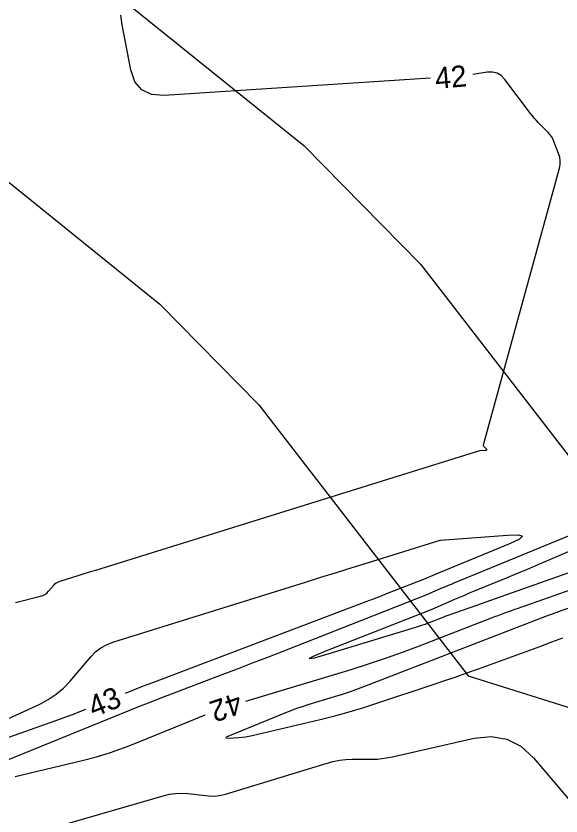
# Model space of a CAD drawing. Extents: x 2384780 to 2405861, y 547869 to 573706.
# Drawn here: x 2389996.9 to 2390047.8, y 552537.2 to 552612 of the extents above; entities that cross this region are included whole.
import ezdxf

# ---------------------------------------------------------------- set-up
doc = ezdxf.new("R2010")
doc.units = 0
for name, color, linetype in [('Old_Level_60', 7, 'Continuous'), ('Prop Buffer Zone 1', 7, 'Continuous'), ('Prop Buffer Zone 2', 7, 'Continuous')]:
    doc.layers.add(name, color=color, linetype=linetype)

msp = doc.modelspace()

# ---------------------------------------------------------------- linework, layer by layer
at = {"layer": 'Old_Level_60'}
for points in [[(2390035.611, 552606.14625), (2390010.736, 552604.53775), (2390009.56225, 552604.6245), (2390008.653, 552605.05375), (2390008.00825, 552605.82525), (2390007.62825, 552606.93925), (2390006.81925, 552611.13775), (2390006.67725, 552612.039)], [(2389996.85825, 552557.1455), (2389999.17375, 552557.72175), (2389999.39, 552557.793), (2389999.58775, 552557.8945), (2389999.7665, 552558.02625), (2389999.92675, 552558.18825), (2390000.41925, 552558.767), (2390000.531, 552558.88175), (2390000.65525, 552558.97725), (2390000.792, 552559.05425), (2390000.94125, 552559.11225), (2390002.7825, 552559.687), (2390003.17725, 552559.81), (2390003.57175, 552559.933), (2390003.9665, 552560.056), (2390004.361, 552560.179), (2390040.23375, 552571.3425), (2390040.23375, 552571.3425), (2390040.23375, 552571.3425), (2390040.23375, 552571.3425), (2390040.23375, 552571.3425), (2390040.234, 552571.3425), (2390040.234, 552571.3425), (2390040.234, 552571.3425), (2390040.234, 552571.3425), (2390040.234, 552571.3425), (2390040.804, 552571.38575), (2390040.86875, 552571.398), (2390040.8975, 552571.42275), (2390040.88975, 552571.45975), (2390040.8455, 552571.509), (2390040.642, 552571.69), (2390040.60575, 552571.731), (2390040.58425, 552571.77625), (2390040.57775, 552571.826), (2390040.58575, 552571.88), (2390047.6805, 552597.74025), (2390047.7485, 552598.0925), (2390047.7585, 552598.4415), (2390047.7105, 552598.78725), (2390047.6045, 552599.13), (2390047.16375, 552600.24425), (2390047.05875, 552600.47625), (2390046.9325, 552600.6945), (2390046.78525, 552600.899), (2390046.61675, 552601.08975), (2390045.70825, 552602.02325), (2390045.517, 552602.22625), (2390045.3325, 552602.435), (2390045.1545, 552602.64925), (2390044.98325, 552602.86925), (2390042.58725, 552606.0485), (2390042.24975, 552606.40125), (2390041.86225, 552606.62975), (2390041.42475, 552606.7345), (2390040.937, 552606.71525), (2390039.593, 552606.50225)], [(2390062.94525, 552568.0865), (2390046.32475, 552560.94525), (2390045.45975, 552560.5755), (2390044.5935, 552560.20925), (2390043.72575, 552559.846), (2390042.85675, 552559.48625), (2390039.71475, 552558.19275), (2390039.2565, 552558.00275), (2390038.7995, 552557.8105), (2390038.34325, 552557.61575), (2390037.88825, 552557.4185), (2390035.76775, 552556.4935), (2390035.76725, 552556.49325), (2390035.76675, 552556.493), (2390035.76625, 552556.49275), (2390035.76575, 552556.49275), (2390035.76425, 552556.492), (2390035.76375, 552556.492), (2390035.7635, 552556.49175), (2390035.76325, 552556.49175), (2390035.76275, 552556.4915), (2390026.063, 552552.67275), (2390024.72875, 552552.12625), (2390024.30125, 552551.895), (2390024.78, 552551.979), (2390026.1655, 552552.37775), (2390033.94, 552554.73), (2390034.342, 552554.85575), (2390034.7415, 552554.989), (2390035.13825, 552555.13), (2390035.5325, 552555.2785), (2390036.816, 552555.77575), (2390037.09125, 552555.88125), (2390037.3675, 552555.9845), (2390037.6445, 552556.08575), (2390037.92225, 552556.185), (2390039.95475, 552556.90075), (2390040.39025, 552557.05425), (2390040.82575, 552557.20775), (2390041.26125, 552557.361), (2390041.697, 552557.5145), (2390053.17325, 552561.55725)], [(2390053.189, 552565.2745), (2390037.81475, 552558.94525), (2390037.551, 552558.836), (2390037.2875, 552558.725), (2390037.02475, 552558.61275), (2390036.76275, 552558.49925), (2390035.5445, 552557.96775), (2390035.5425, 552557.967), (2390035.5405, 552557.96625), (2390035.5385, 552557.96525), (2390035.5365, 552557.9645), (2390035.53, 552557.962), (2390035.5285, 552557.9615), (2390035.527, 552557.961), (2390035.52575, 552557.9605), (2390035.52425, 552557.96), (2390021.82, 552552.5645), (2390020.40125, 552552.00825), (2390018.98075, 552551.4565), (2390017.5585, 552550.909), (2390016.1345, 552550.366), (2390011.4805, 552548.599), (2390010.48425, 552548.21775), (2390009.49025, 552547.83075), (2390008.4985, 552547.43825), (2390007.50875, 552547.04025), (2389994.6135, 552541.81225)], [(2389989.377, 552543.18375), (2389999.10925, 552547.6485), (2389999.909, 552548.06825), (2390000.649, 552548.5665), (2390001.3295, 552549.1435), (2390001.95075, 552549.799), (2390003.8825, 552552.069), (2390004.32075, 552552.51825), (2390004.80825, 552552.89375), (2390005.3445, 552553.195), (2390005.92975, 552553.4225), (2390023.93975, 552559.0445), (2390025.39275, 552559.49775), (2390026.84575, 552559.95075), (2390028.299, 552560.4035), (2390029.75225, 552560.856), (2390036.52875, 552562.96475), (2390036.5315, 552562.96575), (2390036.5345, 552562.96675), (2390036.5375, 552562.9675), (2390036.5405, 552562.9685), (2390036.55, 552562.9715), (2390036.552, 552562.972), (2390036.55425, 552562.9725), (2390036.55625, 552562.97275), (2390036.5585, 552562.973), (2390042.829, 552563.44725), (2390043.849, 552563.472), (2390044.2215, 552563.34325), (2390043.9465, 552563.06075), (2390043.02425, 552562.6245), (2390035.915, 552559.69775), (2390035.84525, 552559.669), (2390035.77575, 552559.63975), (2390035.70625, 552559.61), (2390035.637, 552559.58), (2390035.32125, 552559.44225), (2390035.31775, 552559.44075), (2390035.31425, 552559.43925), (2390035.31075, 552559.43775), (2390035.30725, 552559.4365), (2390035.2955, 552559.432), (2390035.29325, 552559.43125), (2390035.29075, 552559.43025), (2390035.28825, 552559.42925), (2390035.28575, 552559.42825), (2390032.22875, 552558.22475), (2390031.5735, 552557.96775), (2390030.91725, 552557.713), (2390030.26025, 552557.46), (2390029.6025, 552557.20925), (2390009.65425, 552549.63575), (2390008.7925, 552549.30575), (2390007.93275, 552548.971), (2390007.09575, 552548.63975)], [(2390018.374, 552547.916), (2390028.211, 552550.89225), (2390029.824, 552551.397), (2390031.42625, 552551.932), (2390033.01825, 552552.49725), (2390034.6, 552553.093), (2390041.3255, 552555.699), (2390041.64125, 552555.82), (2390041.958, 552555.9385), (2390042.2755, 552556.0545), (2390042.594, 552556.16825), (2390043.63575, 552556.535), (2390043.859, 552556.61375), (2390044.08225, 552556.6925), (2390044.3055, 552556.771), (2390044.52875, 552556.84975), (2390053.54325, 552560.02525)], [(2390050.698, 552557.3605), (2390047.57625, 552556.26075), (2390047.4575, 552556.219), (2390047.33875, 552556.177), (2390047.21975, 552556.13525), (2390047.101, 552556.09325), (2390046.71275, 552555.9565), (2390046.62975, 552555.927), (2390046.547, 552555.89675), (2390046.46425, 552555.86575), (2390046.382, 552555.83425), (2390029.62275, 552549.34025), (2390028.883, 552549.0615), (2390028.13825, 552548.797), (2390027.3885, 552548.54675), (2390026.634, 552548.3105), (2390024.16125, 552547.5625), (2390023.6335, 552547.396), (2390023.11025, 552547.217), (2390022.59125, 552547.026), (2390022.07675, 552546.82225), (2390016.69275, 552544.61775), (2390016.54425, 552544.54725), (2390016.50025, 552544.49975), (2390016.56025, 552544.4755), (2390016.7245, 552544.47425)], [(2390016.7245, 552544.47425), (2390017.73425, 552544.52275), (2390018.0425, 552544.54475), (2390018.3485, 552544.58075), (2390018.65275, 552544.63125), (2390018.95475, 552544.696), (2390025.32925, 552546.21625), (2390026.691, 552546.55675), (2390028.04425, 552546.9265), (2390029.38925, 552547.326), (2390030.72575, 552547.7545), (2390035.78925, 552549.4395), (2390036.873, 552549.8045), (2390037.954, 552550.1765), (2390039.03275, 552550.55625), (2390040.1085, 552550.94325), (2390044.92425, 552552.6945), (2390045.9555, 552553.0715), (2390046.98525, 552553.4525), (2390048.01375, 552553.837)], [(2390003.3875, 552547.13975), (2390002.8255, 552546.9155), (2390002.223, 552546.6825), (2390001.61825, 552546.45625), (2390001.011, 552546.2365), (2389985.14525, 552540.5935)], [(2389996.812, 552540.8665), (2390003.06925, 552542.37925), (2390004.40225, 552542.72825), (2390005.719, 552543.12675), (2390007.01975, 552543.575), (2390008.30425, 552544.073), (2390013.51925, 552546.20825), (2390014.587, 552546.63075)], [(2390000.96925, 552536.252), (2390010.66325, 552539.0725), (2390011.23025, 552539.2085), (2390011.80225, 552539.28775), (2390012.37925, 552539.31025), (2390012.96125, 552539.276), (2390014.87075, 552539.072), (2390015.278, 552539.04875), (2390015.6815, 552539.0665), (2390016.08075, 552539.12525), (2390016.47625, 552539.225), (2390025.96925, 552542.1245), (2390026.54475, 552542.278), (2390027.12675, 552542.38875), (2390027.71525, 552542.457), (2390028.31025, 552542.48275), (2390030.2645, 552542.49675), (2390030.682, 552542.511), (2390031.097, 552542.54775), (2390031.50925, 552542.607), (2390031.91875, 552542.68875), (2390039.70075, 552544.4595), (2390041.29825, 552544.629), (2390042.75625, 552544.37775), (2390044.07475, 552543.70625), (2390045.25325, 552542.6145), (2390051.23925, 552535.585)]]:
    msp.add_lwpolyline(points, dxfattribs=at)
at = {"layer": 'Prop Buffer Zone 1'}
msp.add_lwpolyline([(2390005.01475, 552615.02175), (2390023.78025, 552599.87925), (2390034.69825, 552588.785), (2390051.1385, 552567.4905), (2390079.876, 552558.44225)], dxfattribs=at)
at = {"layer": 'Prop Buffer Zone 2'}
msp.add_lwpolyline([(2389991.166, 552600.4975), (2390010.329, 552585.03425), (2390019.601, 552575.6125), (2390039.144, 552550.29925), (2390065.53175, 552541.99075)], dxfattribs=at)

# ---------------------------------------------------------------- texts
at = {"layer": 'Old_Level_60'}
for s, rotation, p in [('42', 5.1073583, (2390036.13575, 552605.14)), ('43', 22.0254972, (2390004.14925, 552546.3705)), ('42', 198.7463444, (2390017.631, 552548.7575))]:
    msp.add_text(s, height=2, rotation=rotation, dxfattribs=at).set_placement(p)

doc.saveas('drawing.dxf')
